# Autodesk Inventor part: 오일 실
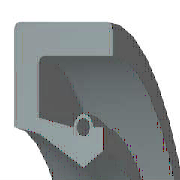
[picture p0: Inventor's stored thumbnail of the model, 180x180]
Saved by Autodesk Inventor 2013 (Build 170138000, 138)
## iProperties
IsCustomPart: 1
Created: 2015-12
Part Number: 오일 실
Material: 고무
Description: 오일-실
Document SubType Name: Modeling
Standard: KS B 2804
Designer: mdu
Standards Organization: KS
Language: ko-KR
Size Designation: S - 15 30 7
Categories: <MemberInstance><Categories><Category DisplayName="샤프트 부품" InternalName="7f7aeb1f-a693-4053-b835-cee3144e0d98" Mnemonic="SHFT"><Category DisplayName="실링" Intern
Density: 0.93 g/cm^3
Author: mdu
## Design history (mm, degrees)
revolve "본체" stored, may be unused: angle "d17" = 90 deg
revolve "스프링1" stored, may be unused: angle "d18" = 90 deg
body "Solid1"
sketch "스케치1"
  geometry: L1 (0, 15)-(7, 15); L2 (7, 15)-(7, 13.75); L3 (7, 13.75)-(1.75, 13.75); L4 (0, 15)-(0, 9.6); L5 (0, 9.6)-(1.75, 9.25); L6 (1.75, 9.25)-(4.9, 7.5); L7 (4.9, 7.5)-(0, 7.5); L8 (6.3, 8.375)-(6.3, 9.6); L9 (0, 0)-(9.586, 0) reference; L10 (4.9, 7.5)-(6.3, 8.375); L11 (0, 18)-(0, -3) reference; L12 (-1.917, 0)-(11.503, 0) reference; L13 (4.2, 9.6)-(1.75, 10.09); L14 (1.75, 10.09)-(1.75, 13.75); L15 (6.3, 9.6)-(5.6, 9.6); C1 r 0.455 at (4.9, 9.6); A1 r 0.7 centre (4.9, 9.6) between (5.6, 9.6) and (4.2, 9.6)
  constraints: 26 end point, 5 horizontal alignment, 4 perpendicular, 2 centre point, 2 collinear, 2 horizontal, 2 parallel, 2 point on circle, 2 point on line, 2 vertical alignment, 1 coincident
  dimensions: "d0" = 30 diameter of L1 L9 (= SD2); "d1" = 16.75 diameter of L8.start L9 (= ABDM); "d2" = 1.25 distance of L1.end L2.end (computed from SD); "d3" = 0.91 diameter of C1 (= SPDI); "d4" = 1.4 diameter of A1 (= SPDA); "d5" = 15 diameter of L6.end L9 (= NND); "d6" = 18.5 diameter of L5.end L9 (= TKDM); "d7" = 19.2 diameter of L4.end L9 (= HLDM); "d8" = 4.9 distance from line of C1.centre L4 (= SPDST); "d9" = 6.3 distance between parallel lines of L8 L4 (= SDI); "d10" = 7 distance between parallel lines of L2 L4 (= SWDT); "d12" = 1.75 distance between parallel lines of L14 L4 (= SD)
fillet "모깎기1" dims "d11" = 0.3 (= RR)
other parameters: "SD2" = 30 [user parameter; used in 1 equation term], "SWDT" = 7 [user parameter; used in 1 equation term], "RR" = 0.3 [user parameter; used in 1 equation term], "SD" = 1.75 [user parameter; used in 2 equation terms], "NND" = 15 [user parameter; used in 1 equation term], "SPDA" = 1.4 [user parameter; used in 1 equation term], "SPDI" = 0.91 [user parameter; used in 1 equation term], "TKDM" = 18.5 [user parameter; used in 1 equation term], "HLDM" = 19.2 [user parameter; used in 1 equation term], "ABDM" = 16.75 [user parameter; used in 1 equation term], "SDI" = 6.3 [user parameter; used in 1 equation term], "SPDST" = 4.9 [user parameter; used in 1 equation term], "d13" = 0, "d14" = 0, "d15" = 0, "LAB" = 0.35 [user parameter]
